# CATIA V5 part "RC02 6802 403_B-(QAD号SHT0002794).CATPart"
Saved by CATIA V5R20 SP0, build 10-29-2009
Part number: RC02 6802 403
Revision: B
Definition: 连接板
Source: Unknown
Property "图纸号": "RC02 6802 403"
Property "材料": "SS440"
Property "规格": "t=3.0"
Property "重量(kg)": "0.0207"
Property "零件类别": "Metallic Part"
Property "项目代码": "H3"
Property "OEM_revision": "A"
Property "OEM_definition": "连接板"
Property "OEM_Source": "0"
Property "OEM_filePath": "RC02 6802 403.CATPart"
Property "OEM_partNumber": "RC02 6802 403"
Bounding box of the stored display mesh (mm): x -432.858 to -412.835, y -903.849 to -848.844, z 321.123 to 324.198
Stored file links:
  C:\TCIC_V5_tmp\catuii\RC02 6802 403_B.CATPart
  D:\工作\CATIA 零件自定义属性_外发_20180807\CATIA 零件自定义属性_外部_20180807.txt
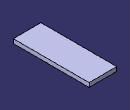
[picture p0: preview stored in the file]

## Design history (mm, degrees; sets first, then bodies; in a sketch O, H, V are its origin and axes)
Body1 "加强块" (main body)
  Solid1: solid without history
Body2 "驾驶员座骨架座框组件\\连接板\\加强块"
  Solid2: solid without history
